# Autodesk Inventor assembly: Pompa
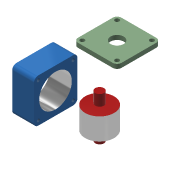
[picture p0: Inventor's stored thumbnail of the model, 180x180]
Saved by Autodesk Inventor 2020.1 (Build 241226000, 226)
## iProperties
Manager: www.cadconsulting.pl
Company: Fabian Stasiak CAD Consulting
Created: 2005-10
Part Number: Pompa
Document SubType Name: Assembly
Designer: F.Stasiak
Author: F.Stasiak
Subject: Zbiór ćwiczeń. Autodesk Inventor 2020. Kurs podstawowy
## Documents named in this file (4)
- C:\2020_Kurs_podstawowy\R6 Zespoły\Kolizja\Pompa.iam
- C:\2020_Kurs_podstawowy\R6 Zespoły\Kolizja\Korpus.ipt
- C:\2020_Kurs_podstawowy\R6 Zespoły\Kolizja\Pokrywka.ipt
- C:\2020_Kurs_podstawowy\R6 Zespoły\Kolizja\Tłok.ipt
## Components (3 placed, 3 different names)
1. Korpus:1
2. Pokrywka:1
3. Tłok:1
